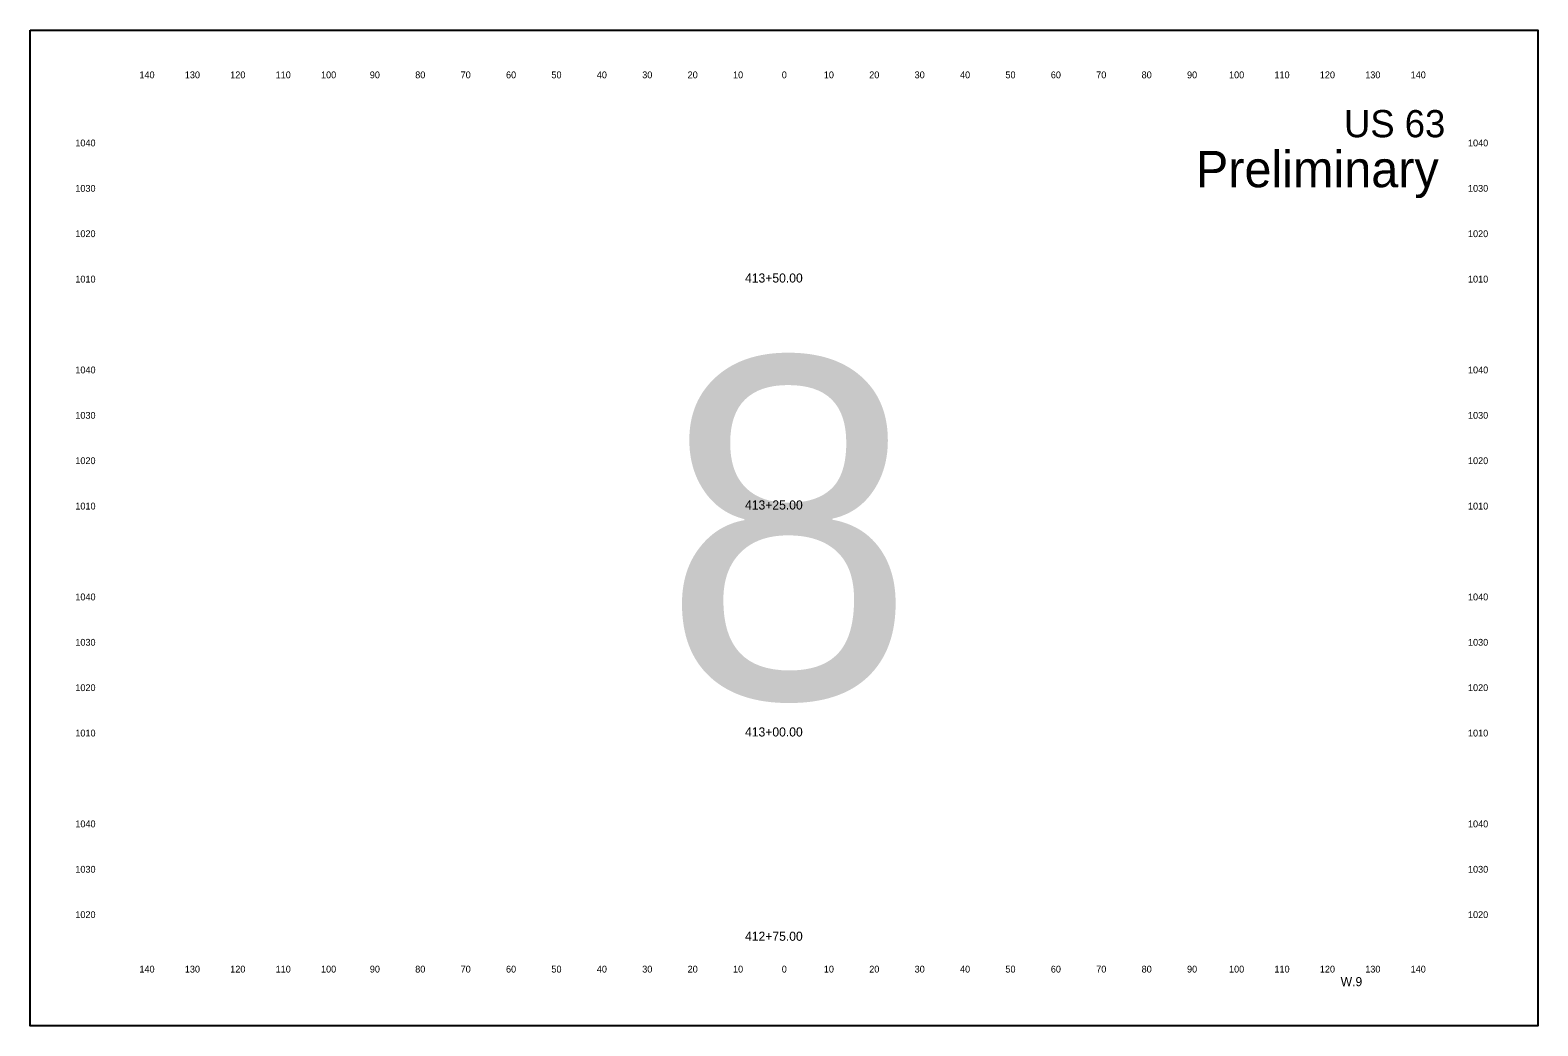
# Model space of a CAD drawing. Extents: x 10123 to 17295, y 9730 to 10181.
# Drawn here: x 12643.2 to 12975.3, y 9730.3 to 9949.6 of the extents above; entities that cross this region are included whole.
import ezdxf

# ---------------------------------------------------------------- set-up
doc = ezdxf.new("R2010")
doc.units = 0
for name, color, linetype in [('dsnTextCpn', 7, 'Continuous'), ('dsnTextCpnTitleSheetLocDesc', 7, 'Continuous'), ('dsnTextCpnTitleSheetPIN', 7, 'Continuous'), ('dsnTextCpnTitleSheetWorkType', 7, 'Continuous')]:
    doc.layers.add(name, color=color, linetype=linetype)

msp = doc.modelspace()

# ---------------------------------------------------------------- linework, layer by layer
at = {"layer": 'dsnTextCpnTitleSheetWorkType'}
msp.add_lwpolyline([(12643.21, 9949.6), (12975.29, 9949.6), (12975.29, 9730.26), (12643.21, 9730.26)], close=True, dxfattribs=at)

# ---------------------------------------------------------------- texts
at = {"layer": 'dsnTextCpn'}
for s, height, p in [('140', 1.5, (12667.27, 9939)), ('130', 1.5, (12677.27, 9939)), ('120', 1.5, (12687.27, 9939)), ('110', 1.5, (12697.27, 9939)), ('100', 1.5, (12707.27, 9939)), ('90', 1.5, (12718.02, 9939)), ('80', 1.5, (12728.02, 9939)), ('70', 1.5, (12738.02, 9939)), ('60', 1.5, (12748.02, 9939)), ('50', 1.5, (12758.02, 9939)), ('40', 1.5, (12768.02, 9939)), ('30', 1.5, (12778.02, 9939)), ('20', 1.5, (12788.02, 9939)), ('10', 1.5, (12798.02, 9939)), ('0', 1.5, (12808.76, 9939)), ('0', 1.5, (12808.76, 9939)), ('10', 1.5, (12818.02, 9939)), ('20', 1.5, (12828.02, 9939)), ('30', 1.5, (12838.02, 9939)), ('40', 1.5, (12848.02, 9939)), ('50', 1.5, (12858.02, 9939)), ('60', 1.5, (12868.02, 9939)), ('70', 1.5, (12878.02, 9939)), ('80', 1.5, (12888.02, 9939)), ('90', 1.5, (12898.02, 9939)), ('100', 1.5, (12907.27, 9939)), ('110', 1.5, (12917.27, 9939)), ('120', 1.5, (12927.27, 9939)), ('130', 1.5, (12937.27, 9939)), ('140', 1.5, (12947.27, 9939)), ('US 63', 6, (12932.6, 9926)), ('1040', 1.5, (12653.15, 9924)), ('1040', 1.5, (12959.9, 9924)), ('1030', 1.5, (12653.15, 9914)), ('1030', 1.5, (12959.9, 9914)), ('1020', 1.5, (12653.15, 9904)), ('1020', 1.5, (12959.9, 9904)), ('1010', 1.5, (12653.15, 9894)), ('413+50.00', 2, (12800.66, 9894)), ('1010', 1.5, (12959.9, 9894)), ('1040', 1.5, (12653.15, 9874)), ('1040', 1.5, (12959.9, 9874)), ('1030', 1.5, (12653.15, 9864)), ('1030', 1.5, (12959.9, 9864)), ('1020', 1.5, (12653.15, 9854)), ('1020', 1.5, (12959.9, 9854)), ('1010', 1.5, (12653.15, 9844)), ('413+25.00', 2, (12800.66, 9844)), ('1010', 1.5, (12959.9, 9844)), ('1040', 1.5, (12653.15, 9824)), ('1040', 1.5, (12959.9, 9824)), ('1030', 1.5, (12653.15, 9814)), ('1030', 1.5, (12959.9, 9814)), ('1020', 1.5, (12653.15, 9804)), ('1020', 1.5, (12959.9, 9804)), ('1010', 1.5, (12653.15, 9794)), ('413+00.00', 2, (12800.66, 9794)), ('1010', 1.5, (12959.9, 9794)), ('1040', 1.5, (12653.15, 9774)), ('1040', 1.5, (12959.9, 9774)), ('1030', 1.5, (12653.15, 9764)), ('1030', 1.5, (12959.9, 9764)), ('1020', 1.5, (12653.15, 9754)), ('1020', 1.5, (12959.9, 9754)), ('412+75.00', 2, (12800.66, 9749)), ('140', 1.5, (12667.27, 9742)), ('130', 1.5, (12677.27, 9742)), ('120', 1.5, (12687.27, 9742)), ('110', 1.5, (12697.27, 9742)), ('100', 1.5, (12707.27, 9742)), ('90', 1.5, (12718.02, 9742)), ('80', 1.5, (12728.02, 9742)), ('70', 1.5, (12738.02, 9742)), ('60', 1.5, (12748.02, 9742)), ('50', 1.5, (12758.02, 9742)), ('40', 1.5, (12768.02, 9742)), ('30', 1.5, (12778.02, 9742)), ('20', 1.5, (12788.02, 9742)), ('10', 1.5, (12798.02, 9742)), ('0', 1.5, (12808.76, 9742)), ('0', 1.5, (12808.76, 9742)), ('10', 1.5, (12818.02, 9742)), ('20', 1.5, (12828.02, 9742)), ('30', 1.5, (12838.02, 9742)), ('40', 1.5, (12848.02, 9742)), ('50', 1.5, (12858.02, 9742)), ('60', 1.5, (12868.02, 9742)), ('70', 1.5, (12878.02, 9742)), ('80', 1.5, (12888.02, 9742)), ('90', 1.5, (12898.02, 9742)), ('100', 1.5, (12907.27, 9742)), ('110', 1.5, (12917.27, 9742)), ('120', 1.5, (12927.27, 9742)), ('130', 1.5, (12937.27, 9742)), ('140', 1.5, (12947.27, 9742))]:
    msp.add_text(s, height=height, dxfattribs=at).set_placement(p)
at = {"layer": 'dsnTextCpnTitleSheetLocDesc'}
msp.add_text('Preliminary', height=8, dxfattribs=at).set_placement((12899.97, 9915))
at = {"layer": 'dsnTextCpnTitleSheetPIN'}
msp.add_text('W.9', height=2, dxfattribs=at).set_placement((12931.86, 9739))
at = {"layer": 'dsnTextCpnTitleSheetWorkType'}
msp.add_text('8', height=75, dxfattribs=at).set_placement((12782.42, 9802.43))

doc.saveas('drawing.dxf')
